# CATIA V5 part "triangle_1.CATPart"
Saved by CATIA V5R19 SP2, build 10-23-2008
Part number: triangle_non_optimise
Definition: triangle_1
Nomenclature: P-00016047
Bounding box of the stored display mesh (mm): x 0 to 50, y -50 to 249.997, z -799.962 to 50
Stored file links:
  C:\Users\matthieu\Desktop\IAO\modele_CAO\triangle_1.CATPart
  U:\IAO\train d'atterrissage.CATProduct
  C:\Users\matthieu\Desktop\IAO\modele_CAO\train_1432.CATProduct
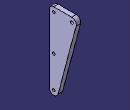
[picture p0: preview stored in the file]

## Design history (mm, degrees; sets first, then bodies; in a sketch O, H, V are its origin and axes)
Body1 (main body)
  Sketch1 on yz-plane, origin (0, 0, 0), H (0, 1, 0), V (0, 0, 1)
    circle A1 centre (0, 0) radius 15
    circle A2 centre (200, 0) radius 15
    point P1 (200, 0)
    circle A3 centre (0, -400) radius 15
    point P2 (0, -400)
    circle A4 centre (0, -750) radius 15
    point P3 (0, -750)
    point P4 (0, 50)
    line L1 (0, 50) -> (200, 50)
    arc A5 centre (200, 0) radius 50 from (200, 50) to (248.3117, -12.8831) cw
    point P6 (200, 0)
    line L2 (248.3117, -12.8831) -> (48.3117, -762.8831)
    arc A6 centre (0, -750) radius 50 from (48.3117, -762.8831) to (-50, -750) cw
    point P9 (0, -750)
    line L3 (-50, -750) -> (-50, 0)
    point P11 (-50, 0)
    arc A7 centre (0, 0) radius 50 from (-50, 0) to (0, 50) cw
    point P12 (0, 0)
    distance P9 P2 = 350
    distance P2 P12 = 400
    distance P6 P12 = 200
    distance L3 V = 50
    radius A1 = 15
    radius A2 = 15
    radius A3 = 15
    radius A4 = 15
    coincidence: P1 H, P2 V, P3 V, P4 V, P11 H
    horizontal: L1 H
    concentricity: A5 A2, A7 A1, A6 A4
    tangency: A5 L1, L2 A5, A6 L2, L3 A6, A7 L3, L1 A7
  Pad1: profile Sketch1, direction (1, 0, 0), length 50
